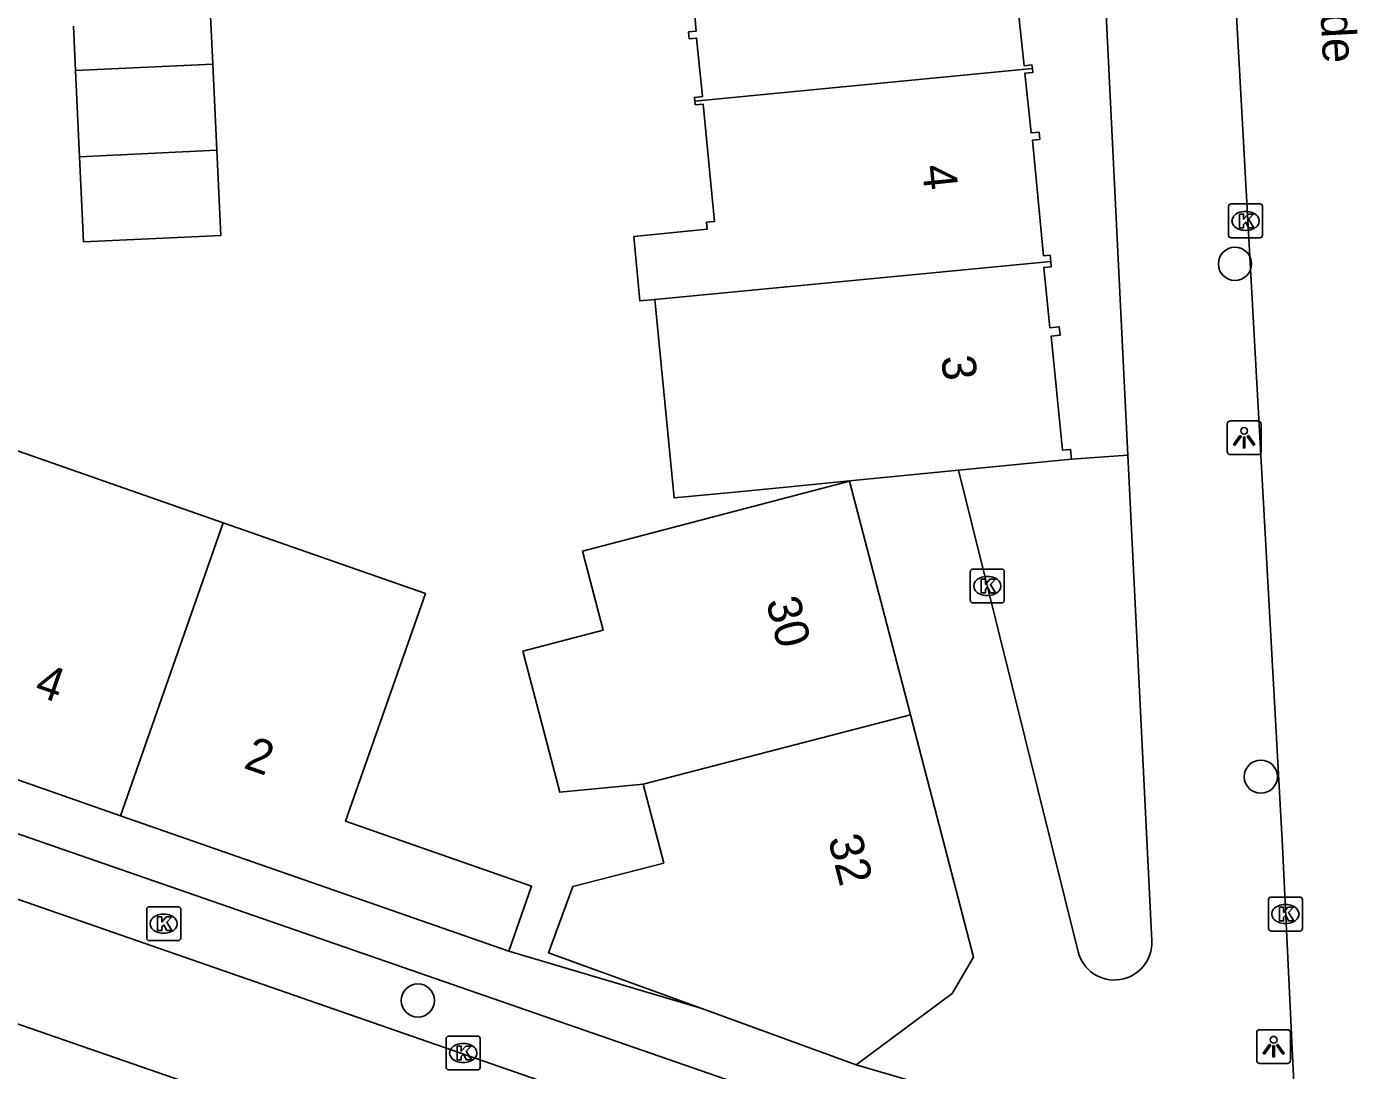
# Model space of a CAD drawing. Extents: x 160026 to 161302, y 384757 to 385701.
# Drawn here: x 160753.58 to 160792.8, y 385208.08 to 385238.85 of the extents above; entities that cross this region are included whole.
import ezdxf

# ---------------------------------------------------------------- set-up
doc = ezdxf.new("R2010")
doc.units = 0
for name, color, linetype in [('IMGEO_Boom', 7, 'Continuous'), ('IMGEO_Groenvoorziening', 7, 'Continuous'), ('IMGEO_Kolk', 7, 'Continuous'), ('IMGEO_Lichtpunt', 7, 'Continuous'), ('IMGEO_Muur', 7, 'Continuous'), ('IMGEO_Openbare_ruimte_label', 7, 'Continuous'), ('IMGEO_Pand', 7, 'Continuous'), ('IMGEO_Pand_nummerreeks', 7, 'Continuous'), ('IMGEO_Rijbaan_lokaal_open', 7, 'Continuous'), ('IMGEO_Voetpad_open', 7, 'Continuous')]:
    doc.layers.add(name, color=color, linetype=linetype)

msp = doc.modelspace()

# ---------------------------------------------------------------- linework, layer by layer
at = {"layer": 'IMGEO_Boom'}
for centre in [(160789.194, 385231.852), (160789.957, 385216.739), (160765.114, 385210.142)]:
    msp.add_circle(centre, 0.489, dxfattribs=at)
at = {"layer": 'IMGEO_Groenvoorziening'}
msp.add_lwpolyline([(160784.378, 385226.098), (160786.035, 385226.217)], dxfattribs=at)
at = {"layer": 'IMGEO_Kolk'}
for p, q in [((160789.005, 385232.694), (160789.005, 385233.546)), ((160789.08, 385233.62), (160789.932, 385233.62)), ((160789.493, 385233.4), (160789.518, 385233.4)), ((160790.006, 385233.546), (160790.006, 385232.694)), ((160789.516, 385232.84), (160789.491, 385232.84)), ((160789.932, 385232.62), (160789.08, 385232.62)), ((160781.395, 385221.933), (160781.395, 385222.785)), ((160781.47, 385222.859), (160782.322, 385222.859)), ((160782.396, 385222.785), (160782.396, 385221.933)), ((160781.883, 385222.639), (160781.908, 385222.639)), ((160782.322, 385221.859), (160781.47, 385221.859)), ((160781.906, 385222.079), (160781.881, 385222.079)), ((160757.197, 385212.907), (160758.049, 385212.907)), ((160790.182, 385212.265), (160790.182, 385213.117)), ((160790.257, 385213.191), (160791.109, 385213.191)), ((160790.67, 385212.971), (160790.695, 385212.971)), ((160791.183, 385213.117), (160791.183, 385212.265)), ((160757.122, 385211.981), (160757.122, 385212.833)), ((160757.61, 385212.687), (160757.635, 385212.687)), ((160758.123, 385212.833), (160758.123, 385211.981)), ((160757.633, 385212.127), (160757.608, 385212.127)), ((160791.109, 385212.191), (160790.257, 385212.191)), ((160790.693, 385212.411), (160790.668, 385212.411)), ((160758.049, 385211.907), (160757.197, 385211.907)), ((160765.949, 385208.17), (160765.949, 385209.022)), ((160766.024, 385209.096), (160766.876, 385209.096)), ((160766.95, 385209.022), (160766.95, 385208.17)), ((160766.437, 385208.876), (160766.462, 385208.876)), ((160766.46, 385208.316), (160766.435, 385208.316)), ((160766.876, 385208.096), (160766.024, 385208.096))]:
    msp.add_line(p, q, dxfattribs=at)
for points in [[(160789.005, 385232.694), (160789.005, 385233.546)], [(160789.08, 385233.62), (160789.932, 385233.62)], [(160789.326, 385233.32), (160789.449, 385233.32), (160789.449, 385233.169), (160789.579, 385233.32), (160789.743, 385233.32), (160789.597, 385233.169), (160789.75, 385232.92), (160789.598, 385232.92), (160789.513, 385233.084), (160789.449, 385233.017), (160789.449, 385232.92), (160789.326, 385232.92), (160789.326, 385233.32)], [(160790.006, 385233.546), (160790.006, 385232.694)], [(160789.932, 385232.62), (160789.08, 385232.62)], [(160781.395, 385221.933), (160781.395, 385222.785)], [(160781.47, 385222.859), (160782.322, 385222.859)], [(160782.396, 385222.785), (160782.396, 385221.933)], [(160781.716, 385222.559), (160781.839, 385222.559), (160781.839, 385222.408), (160781.969, 385222.559), (160782.133, 385222.559), (160781.987, 385222.408), (160782.14, 385222.159), (160781.988, 385222.159), (160781.903, 385222.323), (160781.839, 385222.256), (160781.839, 385222.159), (160781.716, 385222.159), (160781.716, 385222.559)], [(160782.322, 385221.859), (160781.47, 385221.859)], [(160757.197, 385212.907), (160758.049, 385212.907)], [(160790.182, 385212.265), (160790.182, 385213.117)], [(160790.257, 385213.191), (160791.109, 385213.191)], [(160790.503, 385212.891), (160790.626, 385212.891), (160790.626, 385212.74), (160790.756, 385212.891), (160790.92, 385212.891), (160790.774, 385212.74), (160790.927, 385212.491), (160790.775, 385212.491), (160790.69, 385212.655), (160790.626, 385212.588), (160790.626, 385212.491), (160790.503, 385212.491), (160790.503, 385212.891)], [(160791.183, 385213.117), (160791.183, 385212.265)], [(160757.122, 385211.981), (160757.122, 385212.833)], [(160757.443, 385212.607), (160757.566, 385212.607), (160757.566, 385212.456), (160757.696, 385212.607), (160757.86, 385212.607), (160757.714, 385212.456), (160757.867, 385212.207), (160757.715, 385212.207), (160757.63, 385212.371), (160757.566, 385212.304), (160757.566, 385212.207), (160757.443, 385212.207), (160757.443, 385212.607)], [(160758.123, 385212.833), (160758.123, 385211.981)], [(160791.109, 385212.191), (160790.257, 385212.191)], [(160758.049, 385211.907), (160757.197, 385211.907)], [(160765.949, 385208.17), (160765.949, 385209.022)], [(160766.024, 385209.096), (160766.876, 385209.096)], [(160766.95, 385209.022), (160766.95, 385208.17)], [(160766.27, 385208.796), (160766.393, 385208.796), (160766.393, 385208.645), (160766.523, 385208.796), (160766.687, 385208.796), (160766.541, 385208.645), (160766.694, 385208.396), (160766.542, 385208.396), (160766.457, 385208.56), (160766.393, 385208.493), (160766.393, 385208.396), (160766.27, 385208.396), (160766.27, 385208.796)], [(160766.876, 385208.096), (160766.024, 385208.096)]]:
    msp.add_lwpolyline(points, dxfattribs=at)
for centre, start, end in [((160789.082, 385233.544), 91.552, 178.448), ((160789.082, 385233.544), 91.552, 178.448), ((160789.93, 385233.544), 1.552, 88.448), ((160789.93, 385233.544), 1.552, 88.448), ((160789.082, 385232.696), 181.552, 268.448), ((160789.082, 385232.696), 181.552, 268.448), ((160789.93, 385232.696), 271.552, 358.448), ((160789.93, 385232.696), 271.552, 358.448), ((160781.472, 385222.783), 91.552, 178.448), ((160781.472, 385222.783), 91.552, 178.448), ((160782.32, 385222.783), 1.552, 88.448), ((160782.32, 385222.783), 1.552, 88.448), ((160781.472, 385221.935), 181.552, 268.448), ((160781.472, 385221.935), 181.552, 268.448), ((160782.32, 385221.935), 271.552, 358.448), ((160782.32, 385221.935), 271.552, 358.448), ((160757.199, 385212.831), 91.552, 178.448), ((160757.199, 385212.831), 91.552, 178.448), ((160758.047, 385212.831), 1.552, 88.448), ((160758.047, 385212.831), 1.552, 88.448), ((160790.259, 385213.115), 91.552, 178.448), ((160790.259, 385213.115), 91.552, 178.448), ((160791.107, 385213.115), 1.552, 88.448), ((160791.107, 385213.115), 1.552, 88.448), ((160790.259, 385212.267), 181.552, 268.448), ((160790.259, 385212.267), 181.552, 268.448), ((160791.107, 385212.267), 271.552, 358.448), ((160791.107, 385212.267), 271.552, 358.448), ((160757.199, 385211.983), 181.552, 268.448), ((160757.199, 385211.983), 181.552, 268.448), ((160758.047, 385211.983), 271.552, 358.448), ((160758.047, 385211.983), 271.552, 358.448), ((160766.026, 385209.02), 91.552, 178.448), ((160766.026, 385209.02), 91.552, 178.448), ((160766.874, 385209.02), 1.552, 88.448), ((160766.874, 385209.02), 1.552, 88.448), ((160766.026, 385208.172), 181.552, 268.448), ((160766.026, 385208.172), 181.552, 268.448), ((160766.874, 385208.172), 271.552, 358.448), ((160766.874, 385208.172), 271.552, 358.448)]:
    msp.add_arc(centre, 0.0765, start, end, dxfattribs=at)
for centre, major_axis, ratio, start_param, end_param in [((160789.492, 385233.12), (-0.387, 0.002), 0.722429, 4.712389, 7.853982), ((160789.517, 385233.12), (-0.39, 0.002), 0.717154, 1.570796, 4.712389), ((160781.882, 385222.359), (-0.387, 0.002), 0.722429, 4.712389, 7.853982), ((160781.907, 385222.359), (-0.39, 0.002), 0.717154, 1.570796, 4.712389), ((160790.669, 385212.691), (-0.387, 0.002), 0.722429, 4.712389, 7.853982), ((160790.694, 385212.691), (-0.39, 0.002), 0.717154, 1.570796, 4.712389), ((160757.609, 385212.407), (-0.387, 0.002), 0.722429, 4.712389, 7.853982), ((160757.634, 385212.407), (-0.39, 0.002), 0.717154, 1.570796, 4.712389), ((160766.436, 385208.596), (-0.387, 0.002), 0.722429, 4.712389, 7.853982), ((160766.461, 385208.596), (-0.39, 0.002), 0.717154, 1.570796, 4.712389)]:
    msp.add_ellipse(centre, major_axis=major_axis, ratio=ratio, start_param=start_param, end_param=end_param, dxfattribs=at)
at = {"layer": 'IMGEO_Lichtpunt'}
for p, q in [((160788.966, 385227.133), (160788.966, 385226.326)), ((160788.966, 385227.133), (160788.966, 385226.326)), ((160789.868, 385227.228), (160789.06, 385227.228)), ((160789.868, 385227.228), (160789.06, 385227.228)), ((160789.962, 385226.326), (160789.962, 385227.133)), ((160789.962, 385226.326), (160789.962, 385227.133)), ((160789.06, 385226.232), (160789.868, 385226.232)), ((160789.06, 385226.232), (160789.868, 385226.232)), ((160789.836, 385209.188), (160789.836, 385208.381)), ((160789.836, 385209.188), (160789.836, 385208.381)), ((160790.738, 385209.283), (160789.93, 385209.283)), ((160790.738, 385209.283), (160789.93, 385209.283)), ((160790.832, 385208.381), (160790.832, 385209.188)), ((160790.832, 385208.381), (160790.832, 385209.188)), ((160789.93, 385208.287), (160790.738, 385208.287)), ((160789.93, 385208.287), (160790.738, 385208.287))]:
    msp.add_line(p, q, dxfattribs=at)
for points in [[(160789.34, 385226.797), (160789.379, 385226.769), (160789.191, 385226.507), (160789.153, 385226.534), (160789.34, 385226.797)], [(160789.442, 385226.749), (160789.489, 385226.749), (160789.489, 385226.427), (160789.442, 385226.427), (160789.442, 385226.749)], [(160789.552, 385226.769), (160789.59, 385226.796), (160789.777, 385226.534), (160789.738, 385226.506), (160789.552, 385226.769)], [(160790.21, 385208.852), (160790.249, 385208.824), (160790.061, 385208.562), (160790.023, 385208.589), (160790.21, 385208.852)], [(160790.312, 385208.804), (160790.359, 385208.804), (160790.359, 385208.482), (160790.312, 385208.482), (160790.312, 385208.804)], [(160790.422, 385208.824), (160790.46, 385208.851), (160790.647, 385208.589), (160790.608, 385208.561), (160790.422, 385208.824)]]:
    msp.add_lwpolyline(points, dxfattribs=at)
for centre in [(160789.465, 385226.931), (160790.335, 385208.986)]:
    msp.add_circle(centre, 0.0994, dxfattribs=at)
for centre, start, end in [((160789.06, 385227.133), 90, 180), ((160789.06, 385227.133), 90, 180), ((160789.868, 385227.133), 0, 90), ((160789.868, 385227.133), 0, 90), ((160789.06, 385226.326), 180, 270), ((160789.06, 385226.326), 180, 270), ((160789.868, 385226.326), 270, 0), ((160789.868, 385226.326), 270, 360), ((160789.93, 385209.188), 90, 180), ((160789.93, 385209.188), 90, 180), ((160790.738, 385209.188), 0, 90), ((160790.738, 385209.188), 0, 90), ((160789.93, 385208.381), 180, 270), ((160789.93, 385208.381), 180, 270), ((160790.738, 385208.381), 270, 0), ((160790.738, 385208.381), 270, 360)]:
    msp.add_arc(centre, 0.0946, start, end, dxfattribs=at)
at = {"layer": 'IMGEO_Muur'}
msp.add_lwpolyline([(160767.797, 385211.6), (160773.479, 385209.904)], dxfattribs=at)
at = {"layer": 'IMGEO_Pand'}
for points in [[(160783.223, 385237.607), (160783.212, 385237.716), (160782.979, 385237.694), (160782.621, 385241.097), (160782.858, 385241.12), (160782.828, 385241.304), (160782.583, 385241.284), (160782.414, 385243.154), (160782.705, 385243.182), (160782.694, 385243.291)], [(160772.739, 385242.333), (160772.75, 385242.224), (160773, 385242.248), (160773.311, 385238.714), (160773.09, 385238.692), (160773.11, 385238.485), (160773.327, 385238.506), (160773.497, 385236.782), (160773.266, 385236.759), (160773.277, 385236.65)], [(160759.072, 385237.74), (160758.947, 385240.381), (160754.897, 385240.237)], [(160754.963, 385238.863), (160755.025, 385237.549)], [(160755.025, 385237.549), (160759.072, 385237.74)], [(160755.025, 385237.549), (160755.144, 385235.01)], [(160759.192, 385235.201), (160759.072, 385237.74)], [(160773.277, 385236.65), (160783.223, 385237.607)], [(160783.766, 385231.925), (160783.748, 385232.108), (160783.556, 385232.089), (160783.223, 385235.498), (160783.443, 385235.52), (160783.422, 385235.738), (160783.187, 385235.715), (160783.002, 385237.475), (160783.234, 385237.498), (160783.223, 385237.607)], [(160773.277, 385236.65), (160773.288, 385236.541), (160773.518, 385236.563), (160773.859, 385233.102), (160773.619, 385233.079), (160773.639, 385232.871), (160771.474, 385232.659), (160771.659, 385230.76), (160772.095, 385230.802)], [(160755.144, 385235.01), (160755.262, 385232.5), (160759.31, 385232.691), (160759.192, 385235.201)], [(160759.192, 385235.201), (160755.144, 385235.01)], [(160783.766, 385231.925), (160772.095, 385230.802)], [(160784.378, 385226.098), (160784.35, 385226.387), (160784.11, 385226.363), (160783.782, 385229.724), (160784.04, 385229.749), (160784.016, 385229.999), (160783.739, 385229.972), (160783.565, 385231.748), (160783.781, 385231.769), (160783.766, 385231.925)], [(160772.095, 385230.802), (160772.665, 385224.953), (160774.458, 385225.128), (160776.069, 385225.286), (160777.832, 385225.458)], [(160759.375, 385224.223), (160753.146, 385226.405), (160751.772, 385222.481), (160750.119, 385217.762)], [(160781.047, 385225.772), (160784.378, 385226.098)], [(160777.835, 385225.445), (160769.962, 385223.39), (160770.571, 385221.056), (160768.209, 385220.44), (160769.294, 385216.28), (160771.755, 385216.515)], [(160781.047, 385225.772), (160777.832, 385225.458)], [(160777.835, 385225.445), (160779.628, 385218.567)], [(160759.375, 385224.223), (160756.351, 385215.59)], [(160767.797, 385211.6), (160768.467, 385213.51), (160762.985, 385215.424), (160765.335, 385222.136), (160759.375, 385224.223)], [(160779.628, 385218.567), (160771.755, 385216.515)], [(160779.628, 385218.567), (160781.49, 385211.425), (160780.858, 385210.348), (160778.033, 385208.249)], [(160756.351, 385215.59), (160750.119, 385217.762)], [(160771.755, 385216.515), (160772.361, 385214.19), (160769.678, 385213.501), (160768.967, 385211.544), (160773.479, 385209.904)], [(160767.797, 385211.6), (160756.351, 385215.59)], [(160778.033, 385208.249), (160773.479, 385209.904)]]:
    msp.add_lwpolyline(points, dxfattribs=at)
at = {"layer": 'IMGEO_Rijbaan_lokaal_open'}
for points in [[(160791.09, 385204.425), (160790.595, 385214.684), (160788.644, 385250), (160788.518, 385256.641), (160788.484, 385257.309), (160788.404, 385258.674)], [(160728.965, 385221.591), (160783.288, 385202.713)], [(160782.111, 385199.477), (160727.822, 385218.288)]]:
    msp.add_lwpolyline(points, dxfattribs=at)
at = {"layer": 'IMGEO_Voetpad_open'}
for points in [[(160784.613, 385255.119), (160784.865, 385250), (160786.035, 385226.217)], [(160786.035, 385226.217), (160786.74, 385211.9)], [(160777.832, 385225.458), (160777.835, 385225.445)], [(160784.575, 385211.58), (160781.047, 385225.772)], [(160727.342, 385224.065), (160783.445, 385204.608), (160782.993, 385203.324)], [(160773.479, 385209.904), (160767.797, 385211.6)], [(160778.033, 385208.249), (160784.154, 385206.456), (160791.09, 385204.425)]]:
    msp.add_lwpolyline(points, dxfattribs=at)
msp.add_arc((160785.642, 385211.845), 1.099, 193.9219, 2.8936, dxfattribs=at)

# ---------------------------------------------------------------- texts
at = {"layer": 'IMGEO_Openbare_ruimte_label'}
msp.add_text('de Greide', height=1, rotation=273.0369, dxfattribs=at).set_placement((160791.484, 385243.613))
at = {"layer": 'IMGEO_Pand_nummerreeks'}
for s, rotation, p in [('4', 275.7523, (160779.97, 385234.737)), ('3', 275.7523, (160780.536, 385229.118)), ('30', 284.6102, (160775.367, 385221.909)), ('4', 340.783, (160753.774, 385219.157)), ('2', 340.783, (160759.944, 385217.006)), ('32', 284.6102, (160777.193, 385214.904))]:
    msp.add_text(s, height=1, rotation=rotation, dxfattribs=at).set_placement(p)

doc.saveas('drawing.dxf')
